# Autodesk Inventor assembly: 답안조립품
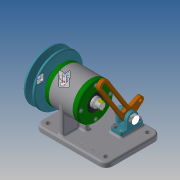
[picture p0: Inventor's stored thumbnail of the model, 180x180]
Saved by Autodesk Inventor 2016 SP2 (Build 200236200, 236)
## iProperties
Created: 2019-09
Part Number: 답안조립품
Document SubType Name: Assembly
Designer: EZ
Author: EZ
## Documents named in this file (19)
- Y:\390904V1057 배철윤\답안조립품.iam
- Y:\390904V1057 배철윤\본체.ipt
- Y:\390904V1057 배철윤\베어링 6004.ipt
- Y:\390904V1057 배철윤\축.ipt
- Y:\390904V1057 배철윤\커버.ipt
- Y:\390904V1057 배철윤\오일 실 17 30 5.ipt
- Y:\390904V1057 배철윤\볼트 M4.ipt
- Y:\390904V1057 배철윤\V-벨트풀리.ipt
- Y:\390904V1057 배철윤\키 5 x 5 x 12.ipt
- Y:\390904V1057 배철윤\키 4 x 4 x 8.ipt
- Y:\390904V1057 배철윤\너트 M10x1.ipt
- Y:\390904V1057 배철윤\돌림판.ipt
- Y:\390904V1057 배철윤\멈춤나사 M3x5.ipt
- Y:\390904V1057 배철윤\크랭크.ipt
- Y:\390904V1057 배철윤\힌지.ipt
- Y:\390904V1057 배철윤\핀 3 x 8.ipt
- Y:\390904V1057 배철윤\힌지 축.ipt
- Y:\390904V1057 배철윤\너트 M8.ipt
- Y:\390904V1057 배철윤\와셔 8x15.5.ipt
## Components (3 placed, 2 different names)
1. V-벨트풀리:1
2. 핀 3 x 8:1 — 플러쉬:2
3. 핀 3 x 8:2 — 플러쉬:3
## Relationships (2: Flush 2)
- 플러쉬:2 [Flush]: 핀 3 x 8:1
- 플러쉬:3 [Flush]: 핀 3 x 8:2
